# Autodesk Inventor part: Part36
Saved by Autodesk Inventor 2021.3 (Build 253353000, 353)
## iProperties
Created: 2021-12
Part Number: Part36
Material: Generic
Document SubType Name: Modeling
Designer: Administrator
Density: 1 g/cm^3
Appearance: Default
Author: Administrator
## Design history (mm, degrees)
feature "本体" [SW]
feature "底板" [SW]
feature "SW1"
feature "SW2"
body "Solid1"
body "Solid2"
body "Solid3"
body "Solid4"
